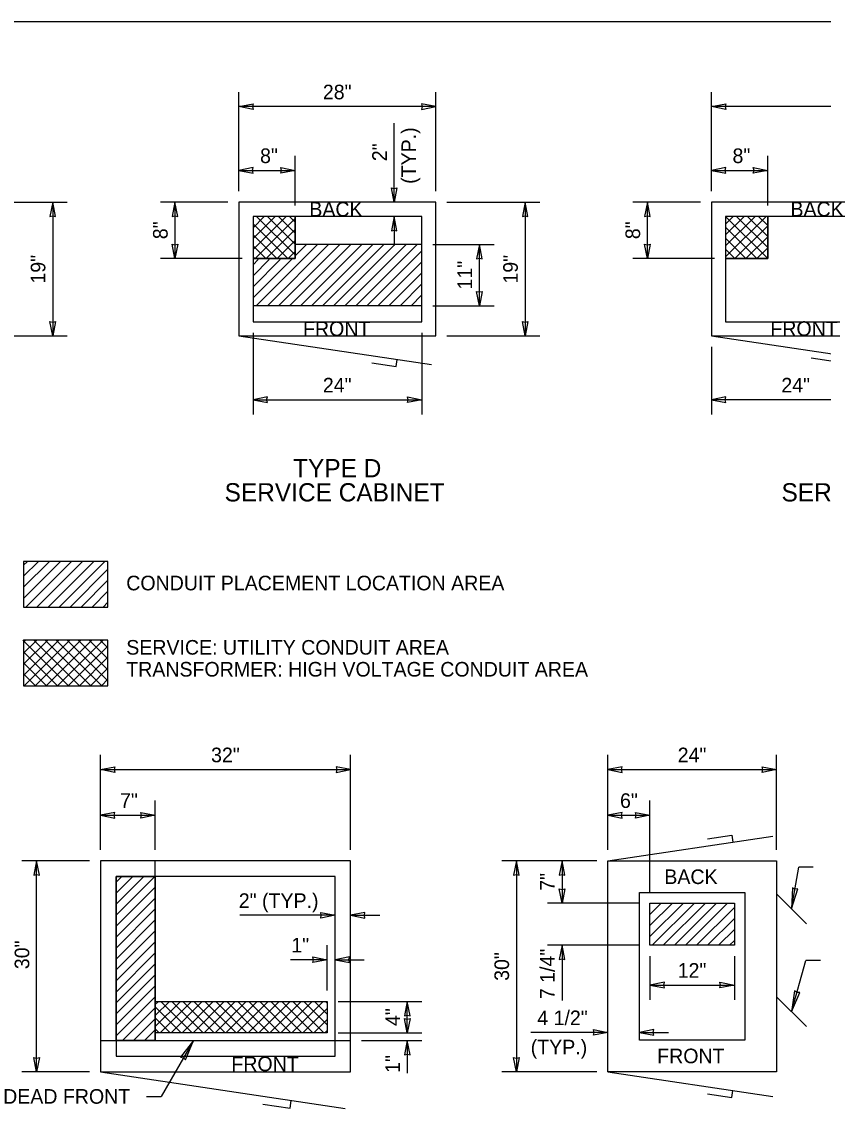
# Model space of a CAD drawing. Extents: x 99862 to 103151, y 100000 to 117076.
# Drawn here: x 100465 to 101342, y 100884 to 102076 of the extents above; entities that cross this region are included whole.
import ezdxf

# ---------------------------------------------------------------- set-up
doc = ezdxf.new("R2010")
doc.units = 0
for name, color, linetype in [('Level 1', 7, 'Continuous'), ('Level 15', 7, 'Continuous'), ('Level 2', 7, 'Continuous'), ('Level 20', 7, 'Continuous'), ('Level 25', 7, 'Continuous'), ('Level 3', 7, 'Continuous'), ('Level 40', 7, 'Continuous'), ('Level 6', 7, 'Continuous'), ('Level 9', 7, 'Continuous')]:
    doc.layers.add(name, color=color, linetype=linetype)

msp = doc.modelspace()

# ---------------------------------------------------------------- linework, layer by layer
at = {"layer": 'Level 1'}
msp.add_lwpolyline([(99862, 99999.5), (103151, 99999.5), (103151, 102075.5), (99862, 102075.5)], close=True, dxfattribs=at)
at = {"layer": 'Level 15'}
for p, q in [((100702.8, 101889.9), (100702.8, 101998.6)), ((100918.2, 101889.9), (100918.2, 101998.6)), ((101219.7, 101889.9), (101219.7, 101998.6)), ((100918.2, 101982.6), (100702.8, 101982.6)), ((101619.8, 101982.6), (101219.7, 101982.6)), ((100872.6, 101877.9), (100872.6, 101964.5)), ((100702.8, 101889.9), (100702.8, 101928.8)), ((100764.3, 101874.5), (100764.3, 101928.8)), ((101219.7, 101889.9), (101219.7, 101928.8)), ((101281.3, 101874.5), (101281.3, 101928.8)), ((100702.8, 101912.8), (100764.3, 101912.8)), ((101219.7, 101912.8), (101281.3, 101912.8)), ((100413.3, 101877.9), (100515, 101877.9)), ((100499, 101877.9), (100499, 101731.7)), ((100690.8, 101877.9), (100616.8, 101877.9)), ((100632.8, 101877.9), (100632.8, 101816.4)), ((100930.2, 101877.9), (101031.9, 101877.9)), ((101015.9, 101877.9), (101015.9, 101731.7)), ((101207.7, 101877.9), (101133.7, 101877.9)), ((101149.7, 101816.4), (101149.7, 101877.9)), ((100872.6, 101862.5), (100872.6, 101830.5)), ((100914.8, 101831.7), (100981.9, 101831.7)), ((100965.9, 101764.7), (100965.9, 101831.7)), ((100706.2, 101816.4), (100616.8, 101816.4)), ((101223.1, 101816.4), (101133.7, 101816.4)), ((100914.8, 101764.7), (100981.9, 101764.7)), ((100718.2, 101735.1), (100718.2, 101645.7)), ((100902.8, 101735.1), (100902.8, 101645.7)), ((100413.3, 101731.7), (100515, 101731.7)), ((100930.2, 101731.7), (101031.9, 101731.7)), ((101219.7, 101719.7), (101219.7, 101645.7)), ((100718.2, 101661.7), (100902.8, 101661.7)), ((101404.4, 101661.7), (101219.7, 101661.7)), ((100551.4, 101168.9), (100551.4, 101272.9)), ((100825, 101168.9), (100825, 101272.9)), ((101106.3, 101168.9), (101106.3, 101272.9)), ((101291, 101168.9), (101291, 101272.9)), ((100551.4, 101256.9), (100825, 101256.9)), ((101106.3, 101256.9), (101291, 101256.9)), ((100611.2, 101168.9), (100611.2, 101222.9)), ((101152.5, 101122.7), (101152.5, 101222.9)), ((100553.4, 101206.9), (100611.2, 101206.9)), ((101106.3, 101206.9), (101152.5, 101206.9)), ((100539.4, 101156.9), (100465.4, 101156.9)), ((100481.4, 100926.1), (100481.4, 101156.9)), ((101094.3, 101156.9), (100990.3, 101156.9)), ((101006.3, 101156.9), (101006.3, 100926.1)), ((101056.3, 101156.9), (101056.3, 101110.7)), ((101307.3, 101104.4), (101315.2, 101149.9)), ((101331.2, 101149.9), (101315.2, 101149.9)), ((101140.5, 101110.7), (101040.3, 101110.7)), ((100807.9, 101097.4), (100703.7, 101097.4)), ((100825, 101097.4), (100857, 101097.4)), ((100799.3, 101015), (100799.3, 101064.7)), ((101140.5, 101064.6), (101040.3, 101064.6)), ((101056.3, 101064.6), (101056.3, 101004.1)), ((100799.3, 101048.7), (100759.2, 101048.7)), ((100807.9, 101048.7), (100839.9, 101048.7)), ((101152.5, 101052.6), (101152.5, 101005)), ((101244.8, 101052.6), (101244.8, 101005)), ((101307.3, 100991.8), (101323.1, 101047.8)), ((101339.1, 101047.8), (101323.1, 101047.8)), ((101152.5, 101021), (101244.8, 101021)), ((100811.3, 101003), (100903, 101003)), ((100887, 100968.8), (100887, 101003)), ((100653, 100960.3), (100617.7, 100899.1)), ((100811.3, 100968.8), (100903, 100968.8)), ((100837, 100960.3), (100903, 100960.3)), ((100887, 100960.3), (100887, 100924.6)), ((101106.3, 100969.1), (101022.3, 100969.1)), ((101140.9, 100969.1), (101172.9, 100969.1)), ((100539.4, 100926.1), (100465.4, 100926.1)), ((101094.3, 100926.1), (100990.3, 100926.1)), ((100601.7, 100899.1), (100617.7, 100899.1))]:
    msp.add_line(p, q, dxfattribs=at)
for points in [[(100702.8, 101982.6), (100718.5, 101985.7), (100717.8, 101982.6), (100718.5, 101979.5)], [(100918.2, 101982.6), (100902.5, 101985.7), (100903.2, 101982.6), (100902.5, 101979.5)], [(101219.7, 101982.6), (101235.4, 101985.6), (101234.7, 101982.6), (101235.4, 101979.5)], [(100702.8, 101912.8), (100718.5, 101909.7), (100717.8, 101912.8), (100718.5, 101915.9)], [(100764.3, 101912.8), (100748.6, 101909.7), (100749.3, 101912.8), (100748.6, 101915.9)], [(101219.7, 101912.8), (101235.4, 101909.7), (101234.7, 101912.8), (101235.4, 101915.9)], [(101281.3, 101912.8), (101265.5, 101909.7), (101266.3, 101912.8), (101265.5, 101915.9)], [(100872.6, 101877.9), (100869.6, 101893.6), (100872.6, 101892.9), (100875.7, 101893.6)], [(100499, 101877.9), (100495.9, 101862.2), (100499, 101862.9), (100502.1, 101862.2)], [(100632.8, 101877.9), (100629.7, 101862.2), (100632.8, 101862.9), (100635.8, 101862.2)], [(101015.9, 101877.9), (101012.9, 101862.2), (101015.9, 101862.9), (101019, 101862.2)], [(101149.7, 101877.9), (101146.6, 101862.2), (101149.7, 101862.9), (101152.8, 101862.2)], [(100872.6, 101862.5), (100869.6, 101846.8), (100872.6, 101847.5), (100875.7, 101846.8)], [(100632.8, 101816.4), (100629.7, 101832.1), (100632.8, 101831.4), (100635.8, 101832.1)], [(100965.9, 101831.7), (100962.8, 101816), (100965.9, 101816.7), (100969, 101816)], [(101149.7, 101816.4), (101146.6, 101832.1), (101149.7, 101831.4), (101152.8, 101832.1)], [(100965.9, 101764.7), (100962.8, 101780.4), (100965.9, 101779.7), (100969, 101780.4)], [(100499, 101731.7), (100495.9, 101747.4), (100499, 101746.7), (100502.1, 101747.4)], [(101015.9, 101731.7), (101012.9, 101747.4), (101015.9, 101746.7), (101019, 101747.4)], [(100718.2, 101661.7), (100733.9, 101658.6), (100733.1, 101661.7), (100733.9, 101664.8)], [(100902.8, 101661.7), (100887.1, 101658.6), (100887.8, 101661.7), (100887.1, 101664.8)], [(101219.7, 101661.7), (101235.4, 101658.6), (101234.7, 101661.7), (101235.4, 101664.8)], [(100551.4, 101256.9), (100567.1, 101260), (100566.4, 101256.9), (100567.1, 101253.8)], [(100825, 101256.9), (100809.3, 101260), (100810, 101256.9), (100809.3, 101253.8)], [(101106.3, 101256.9), (101122, 101253.8), (101121.3, 101256.9), (101122, 101260)], [(101291, 101256.9), (101275.3, 101253.8), (101276, 101256.9), (101275.3, 101260)], [(100551.4, 101206.9), (100567.1, 101203.8), (100566.4, 101206.9), (100567.1, 101210)], [(100611.2, 101206.9), (100595.5, 101203.8), (100596.2, 101206.9), (100595.5, 101210)], [(101106.3, 101206.9), (101122, 101203.8), (101121.3, 101206.9), (101122, 101210)], [(101152.5, 101206.9), (101136.7, 101203.8), (101137.5, 101206.9), (101136.7, 101210)], [(100481.4, 101156.9), (100478.3, 101141.2), (100481.4, 101141.9), (100484.5, 101141.2)], [(101006.3, 101156.9), (101003.2, 101141.2), (101006.3, 101141.9), (101009.4, 101141.2)], [(101056.3, 101156.9), (101053.2, 101141.2), (101056.3, 101141.9), (101059.4, 101141.2)], [(101056.3, 101110.7), (101053.2, 101126.5), (101056.3, 101125.7), (101059.4, 101126.5)], [(101307.3, 101104.4), (101314.1, 101126.4), (101311, 101125.9), (101308.3, 101127.4)], [(100807.9, 101097.4), (100792.2, 101094.3), (100792.9, 101097.4), (100792.2, 101100.4)], [(100825, 101097.4), (100840.7, 101094.3), (100840, 101097.4), (100840.7, 101100.4)], [(101056.3, 101064.6), (101053.2, 101048.8), (101056.3, 101049.6), (101059.4, 101048.8)], [(100799.3, 101048.7), (100783.6, 101045.6), (100784.3, 101048.7), (100783.6, 101051.8)], [(100807.9, 101048.7), (100823.6, 101045.6), (100822.9, 101048.7), (100823.6, 101051.8)], [(101152.5, 101021), (101168.2, 101017.9), (101167.5, 101021), (101168.2, 101024.1)], [(101244.8, 101021), (101229.1, 101017.9), (101229.8, 101021), (101229.1, 101024.1)], [(101307.3, 100991.8), (101316.4, 101013), (101313.2, 101012.8), (101310.6, 101014.6)], [(100887, 101003), (100883.9, 100987.3), (100887, 100988), (100890.1, 100987.3)], [(100887, 100968.8), (100883.9, 100984.5), (100887, 100983.8), (100890.1, 100984.5)], [(101106.3, 100969.1), (101090.6, 100966), (101091.3, 100969.1), (101090.6, 100972.2)], [(101140.9, 100969.1), (101156.7, 100966), (101155.9, 100969.1), (101156.7, 100972.2)], [(100653, 100960.3), (100639, 100942), (100642.1, 100941.4), (100644.2, 100939)], [(100887, 100960.3), (100883.9, 100944.5), (100887, 100945.3), (100890.1, 100944.5)], [(100481.4, 100926.1), (100478.3, 100941.8), (100481.4, 100941.1), (100484.5, 100941.8)], [(101006.3, 100926.1), (101003.2, 100941.8), (101006.3, 100941.1), (101009.4, 100941.8)]]:
    msp.add_lwpolyline(points, close=True, dxfattribs=at)
at = {"layer": 'Level 2'}
for p, q in [((100702.8, 101731.7), (100913.5, 101700.2)), ((100848.1, 101702.2), (100874.7, 101698.2)), ((100874.7, 101698.2), (100875.9, 101705.8))]:
    msp.add_line(p, q, dxfattribs=at)
for points in [[(100702.8, 101731.7), (100918.2, 101731.7), (100918.2, 101877.9), (100702.8, 101877.9)], [(100718.2, 101747.1), (100902.8, 101747.1), (100902.8, 101862.5), (100718.2, 101862.5)]]:
    msp.add_lwpolyline(points, close=True, dxfattribs=at)
at = {"layer": 'Level 25'}
for p, q in [((100764.3, 101862.5), (100764.3, 101816.4)), ((101281.3, 101862.5), (101281.3, 101816.4)), ((100721.8, 101764.7), (100788.8, 101831.7)), ((100733.9, 101764.7), (100800.9, 101831.7)), ((100746, 101764.7), (100813, 101831.7)), ((100758.1, 101764.7), (100825.1, 101831.7)), ((100902.8, 101831.7), (100764.3, 101831.7)), ((100764.3, 101819.3), (100776.7, 101831.7)), ((100770.2, 101764.7), (100837.2, 101831.7)), ((100782.2, 101764.7), (100849.3, 101831.7)), ((100794.3, 101764.7), (100861.4, 101831.7)), ((100806.4, 101764.7), (100873.5, 101831.7)), ((100818.5, 101764.7), (100885.6, 101831.7)), ((100830.6, 101764.7), (100897.6, 101831.7)), ((100764.3, 101816.4), (100718.2, 101816.4)), ((100718.2, 101773.2), (100761.3, 101816.4)), ((100842.7, 101764.7), (100902.8, 101824.8)), ((101281.3, 101816.4), (101235.1, 101816.4)), ((100718.2, 101809.4), (100723.8, 101815.1)), ((100718.2, 101797.3), (100735.9, 101815.1)), ((100718.2, 101785.3), (100748, 101815.1)), ((100854.8, 101764.7), (100902.8, 101812.7)), ((100866.9, 101764.7), (100902.8, 101800.7)), ((100879, 101764.7), (100902.8, 101788.6)), ((100891.1, 101764.7), (100902.8, 101776.5)), ((100902.8, 101764.7), (100718.2, 101764.7)), ((100467.1, 101456.4), (100495.6, 101484.8)), ((100467.1, 101444.3), (100507.7, 101484.8)), ((100467.1, 101468.5), (100483.5, 101484.8)), ((100467.1, 101480.6), (100471.4, 101484.8)), ((100469.7, 101434.8), (100519.7, 101484.8)), ((100481.8, 101434.8), (100531.8, 101484.8)), ((100493.9, 101434.8), (100543.9, 101484.8)), ((100506, 101434.8), (100556, 101484.8)), ((100518.1, 101434.8), (100559.5, 101476.3)), ((100530.2, 101434.8), (100559.5, 101464.2)), ((100542.3, 101434.8), (100559.5, 101452.1)), ((100554.4, 101434.8), (100559.5, 101440)), ((100466.4, 101398.7), (100516.4, 101348.6)), ((100467.1, 101372.1), (100493.6, 101398.7)), ((100467.1, 101360), (100505.7, 101398.7)), ((100467.1, 101384.2), (100481.5, 101398.7)), ((100467.1, 101396.3), (100469.4, 101398.7)), ((100467.8, 101348.6), (100517.8, 101398.7)), ((100478.5, 101398.7), (100528.5, 101348.6)), ((100479.9, 101348.6), (100529.9, 101398.7)), ((100490.6, 101398.7), (100540.6, 101348.6)), ((100492, 101348.6), (100542, 101398.7)), ((100502.7, 101398.7), (100552.7, 101348.6)), ((100504.1, 101348.6), (100554.1, 101398.7)), ((100514.8, 101398.7), (100559.5, 101353.9)), ((100526.8, 101398.7), (100559.5, 101366)), ((100538.9, 101398.7), (100559.5, 101378)), ((100551, 101398.7), (100559.5, 101390.1)), ((100516.1, 101348.6), (100559.5, 101392)), ((100467.1, 101385.8), (100504.3, 101348.6)), ((100528.2, 101348.6), (100559.5, 101379.9)), ((100467.1, 101373.8), (100492.2, 101348.6)), ((100540.3, 101348.6), (100559.5, 101367.8)), ((100467.1, 101361.7), (100480.1, 101348.6)), ((100552.4, 101348.6), (100559.5, 101355.7)), ((100467.1, 101349.6), (100468.1, 101348.6)), ((101152.5, 101110.4), (101152.8, 101110.7)), ((101152.5, 101098.3), (101164.9, 101110.7)), ((101152.5, 101086.2), (101177, 101110.7)), ((101152.5, 101074.1), (101189.1, 101110.7)), ((101155, 101064.6), (101201.2, 101110.7)), ((101167.1, 101064.6), (101213.2, 101110.7)), ((101179.2, 101064.6), (101225.3, 101110.7)), ((101191.3, 101064.6), (101237.4, 101110.7)), ((101203.4, 101064.6), (101244.8, 101106)), ((101215.4, 101064.6), (101244.8, 101093.9)), ((101227.5, 101064.6), (101244.8, 101081.8)), ((101239.6, 101064.6), (101244.8, 101069.8)), ((101244.8, 101064.6), (101152.5, 101064.6))]:
    msp.add_line(p, q, dxfattribs=at)
for points in [[(100559.5, 101484.8), (100467.1, 101484.8), (100467.1, 101434.8), (100559.5, 101434.8)], [(100559.5, 101398.7), (100467.1, 101398.7), (100467.1, 101348.6), (100559.5, 101348.6)]]:
    msp.add_lwpolyline(points, close=True, dxfattribs=at)
msp.add_lwpolyline([(101152.5, 101064.6), (101152.5, 101110.7), (101244.8, 101110.7), (101244.8, 101064.6)], dxfattribs=at)
at = {"layer": 'Level 3'}
for p, q in [((101219.7, 101731.7), (101395.3, 101705.4)), ((101328.8, 101707.6), (101355.4, 101703.6))]:
    msp.add_line(p, q, dxfattribs=at)
for points in [[(101219.7, 101731.7), (101619.8, 101731.7), (101619.8, 101877.9), (101219.7, 101877.9)], [(101235.1, 101747.1), (101604.4, 101747.1), (101604.4, 101862.5), (101235.1, 101862.5)]]:
    msp.add_lwpolyline(points, close=True, dxfattribs=at)
at = {"layer": 'Level 40'}
for p, q in [((100718.2, 101826.1), (100754.6, 101862.5)), ((100718.2, 101838.1), (100742.6, 101862.5)), ((100718.2, 101850.1), (100730.5, 101862.5)), ((100718.2, 101862.2), (100718.5, 101862.5)), ((100718.2, 101854.3), (100756.1, 101816.4)), ((100720.4, 101816.4), (100764.3, 101860.2)), ((100721.9, 101862.5), (100764.3, 101820.2)), ((100734, 101862.5), (100764.3, 101832.2)), ((100746, 101862.5), (100764.3, 101844.2)), ((100758, 101862.5), (100764.3, 101856.2)), ((101235.1, 101818.1), (101279.6, 101862.5)), ((101235.1, 101830.1), (101267.5, 101862.5)), ((101235.1, 101842.1), (101255.5, 101862.5)), ((101235.1, 101854.1), (101243.5, 101862.5)), ((101235.2, 101862.5), (101281.3, 101816.5)), ((101245.4, 101816.4), (101281.3, 101852.2)), ((101247.2, 101862.5), (101281.3, 101828.5)), ((101259.3, 101862.5), (101281.3, 101840.5)), ((101271.3, 101862.5), (101281.3, 101852.5)), ((100718.2, 101842.3), (100744.1, 101816.4)), ((100732.5, 101816.4), (100764.3, 101848.2)), ((101235.1, 101850.6), (101269.4, 101816.4)), ((101257.4, 101816.4), (101281.3, 101840.2)), ((100718.2, 101830.3), (100732.1, 101816.4)), ((100744.5, 101816.4), (100764.3, 101836.2)), ((101235.1, 101838.6), (101257.3, 101816.4)), ((101269.4, 101816.4), (101281.3, 101828.2)), ((100718.2, 101818.2), (100720, 101816.4)), ((100756.5, 101816.4), (100764.3, 101824.2)), ((101235.1, 101826.6), (101245.3, 101816.4)), ((100568.5, 101097.6), (100610.7, 101139.8)), ((100568.5, 101109.6), (100598.7, 101139.8)), ((100568.5, 101121.6), (100586.7, 101139.8)), ((100568.5, 101133.7), (100574.6, 101139.8)), ((100568.5, 101085.6), (100611.2, 101128.3)), ((100568.5, 101073.6), (100611.2, 101116.3)), ((100568.5, 101061.5), (100611.2, 101104.3)), ((100568.5, 101049.5), (100611.2, 101092.3)), ((100568.5, 101037.5), (100611.2, 101080.2)), ((100568.5, 101025.5), (100611.2, 101068.2)), ((100568.5, 101013.4), (100611.2, 101056.2)), ((100568.5, 101001.4), (100611.2, 101044.2)), ((100568.5, 100989.4), (100611.2, 101032.2)), ((100568.5, 100977.4), (100611.2, 101020.1)), ((100568.5, 100965.4), (100611.2, 101008.1)), ((100575.4, 100960.3), (100611.2, 100996.1)), ((100611.2, 100975.6), (100638.7, 101003)), ((100611.2, 100987.6), (100626.7, 101003)), ((100611.2, 100999.6), (100614.6, 101003)), ((100611.2, 100997.1), (100639.5, 100968.8)), ((100616.5, 100968.8), (100650.7, 101003)), ((100617.3, 101003), (100651.5, 100968.8)), ((100628.5, 100968.8), (100662.7, 101003)), ((100629.3, 101003), (100663.5, 100968.8)), ((100640.5, 100968.8), (100674.7, 101003)), ((100641.4, 101003), (100675.6, 100968.8)), ((100652.6, 100968.8), (100686.8, 101003)), ((100653.4, 101003), (100687.6, 100968.8)), ((100664.6, 100968.8), (100698.8, 101003)), ((100665.4, 101003), (100699.6, 100968.8)), ((100676.6, 100968.8), (100710.8, 101003)), ((100677.4, 101003), (100711.6, 100968.8)), ((100688.6, 100968.8), (100722.8, 101003)), ((100689.4, 101003), (100723.6, 100968.8)), ((100700.6, 100968.8), (100734.8, 101003)), ((100701.5, 101003), (100735.7, 100968.8)), ((100712.7, 100968.8), (100746.9, 101003)), ((100713.5, 101003), (100747.7, 100968.8)), ((100724.7, 100968.8), (100758.9, 101003)), ((100725.5, 101003), (100759.7, 100968.8)), ((100736.7, 100968.8), (100770.9, 101003)), ((100737.5, 101003), (100771.7, 100968.8)), ((100748.7, 100968.8), (100782.9, 101003)), ((100749.6, 101003), (100783.8, 100968.8)), ((100760.7, 100968.8), (100794.9, 101003)), ((100761.6, 101003), (100795.8, 100968.8)), ((100772.8, 100968.8), (100799.3, 100995.4)), ((100773.6, 101003), (100799.3, 100977.3)), ((100785.6, 101003), (100799.3, 100989.3)), ((100797.6, 101003), (100799.3, 101001.3)), ((100587.4, 100960.3), (100611.2, 100984.1)), ((100611.2, 100985), (100627.5, 100968.8)), ((100784.8, 100968.8), (100799.3, 100983.4)), ((100599.4, 100960.3), (100611.2, 100972.1)), ((100611.2, 100973), (100615.5, 100968.8)), ((100796.8, 100968.8), (100799.3, 100971.3))]:
    msp.add_line(p, q, dxfattribs=at)
for points in [[(100718.2, 101816.4), (100764.3, 101816.4), (100764.3, 101862.5), (100718.2, 101862.5)], [(101235.1, 101816.4), (101281.3, 101816.4), (101281.3, 101862.5), (101235.1, 101862.5)], [(100568.5, 101139.8), (100611.2, 101139.8), (100611.2, 100960.3), (100568.5, 100960.3)], [(100611.2, 101003), (100799.3, 101003), (100799.3, 100968.8), (100611.2, 100968.8)]]:
    msp.add_lwpolyline(points, close=True, dxfattribs=at)
at = {"layer": 'Level 6'}
for p, q in [((101106.3, 101156.9), (101286.9, 101183.9)), ((101215.4, 101181), (101242, 101185)), ((101242, 101185), (101243.2, 101177.4)), ((101323.6, 101088.1), (101291, 101120.7)), ((101323.6, 100975.5), (101291, 101008.1)), ((101106.3, 100926.1), (101286.9, 100899)), ((101215.4, 100901.9), (101242, 100898)), ((101242, 100898), (101243.2, 100905.6))]:
    msp.add_line(p, q, dxfattribs=at)
for points in [[(101106.3, 100926.1), (101106.3, 101156.9), (101291, 101156.9), (101291, 100926.1)], [(101140.9, 100960.7), (101140.9, 101122.3), (101256.4, 101122.3), (101256.4, 100960.7)]]:
    msp.add_lwpolyline(points, close=True, dxfattribs=at)
at = {"layer": 'Level 9'}
for p, q in [((100611.2, 100960.3), (100611.2, 101156.9)), ((100551.4, 100960.3), (100825, 100960.3)), ((100551.4, 100926.1), (100819, 100886)), ((100729.1, 100890.8), (100758.7, 100886.4)), ((100758.7, 100886.4), (100760, 100894.8))]:
    msp.add_line(p, q, dxfattribs=at)
for points in [[(100551.4, 100926.1), (100825, 100926.1), (100825, 101156.9), (100551.4, 101156.9)], [(100568.5, 100943.2), (100807.9, 100943.2), (100807.9, 101139.8), (100568.5, 101139.8)]]:
    msp.add_lwpolyline(points, close=True, dxfattribs=at)

# ---------------------------------------------------------------- texts
at = {"layer": 'Level 20'}
for s, height, p in [('28"', 16, (100794.6, 101990.6)), ('8"', 16, (100725.9, 101920.8)), ('8"', 16, (101242.8, 101920.8)), ('BACK', 16, (100779.8, 101862.3)), ('BACK', 16, (101306.2, 101862.4)), ('FRONT', 16, (100772.9, 101731.5)), ('FRONT', 16, (101284.2, 101731.6)), ('24"', 16, (100794.6, 101669.7)), ('24"', 16, (101296.2, 101669.7)), ('TYPE D', 20, (100762, 101576.8)), ('SERVICE CABINET', 20, (100687.1, 101550.4)), ('SERVICE CABINET', 20, (101296.4, 101550.4)), ('32"', 16, (100672.3, 101264.9)), ('24"', 16, (101182.8, 101264.9)), ('7"', 16, (100572.7, 101215)), ('6"', 16, (101119.7, 101214.9)), ('BACK', 16, (101168.2, 101131.6)), ('2" (TYP.)', 16, (100702.6, 101105.4)), ('1"', 16, (100760.1, 101056.7)), ('12"', 16, (101182.8, 101029)), ('4 1/2"', 16, (101029.2, 100977.1)), ('(TYP.)', 16, (101022, 100945.1)), ('FRONT', 16, (101160.4, 100935.4)), ('FRONT', 16, (100694.5, 100926.7)), ('DEAD FRONT', 16, (100444.8, 100891.1))]:
    msp.add_text(s, height=height, dxfattribs=at).set_placement(p)
for s, rotation, p in [('(TYP.)', 90, (100896.6, 101898.1)), ('2"', 90, (100864.6, 101922.9)), ('8"', 90, (100624.8, 101837.5)), ('8"', 90, (101141.7, 101837.5)), ('19"', 90, (100491, 101788.9)), ('19"', 90, (101007.9, 101788.9)), ('11"', 90, (100957.9, 101782.4)), ('CONDUIT PLACEMENT LOCATION AREA', 360, (100579.5, 101453.1)), ('SERVICE: UTILITY CONDUIT AREA', 360, (100579.5, 101382.7)), ('TRANSFORMER: HIGH VOLTAGE CONDUIT AREA', 360, (100579.5, 101358.7)), ('7"', 90, (101048.3, 101124.2)), ('30"', 90, (100473.4, 101038.4)), ('30"', 90, (100998.3, 101025.6)), ('7 1/4"', 90, (101048.3, 101005.6)), ('4"', 90, (100879, 100976.2)), ('1"', 90, (100879, 100924.9))]:
    msp.add_text(s, height=16, rotation=rotation, dxfattribs=at).set_placement(p)

doc.saveas('drawing.dxf')
